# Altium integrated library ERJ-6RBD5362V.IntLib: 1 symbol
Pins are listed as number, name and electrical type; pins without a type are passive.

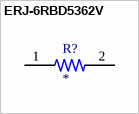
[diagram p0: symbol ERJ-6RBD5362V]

## ERJ-6RBD5362V
designator R?
Thick Film Chip Res,0805, 0.5% Precision 53.6kOhm,; MP: ERJ-6RBD5362V
footprint RESC2012X70
pins: 1, 2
